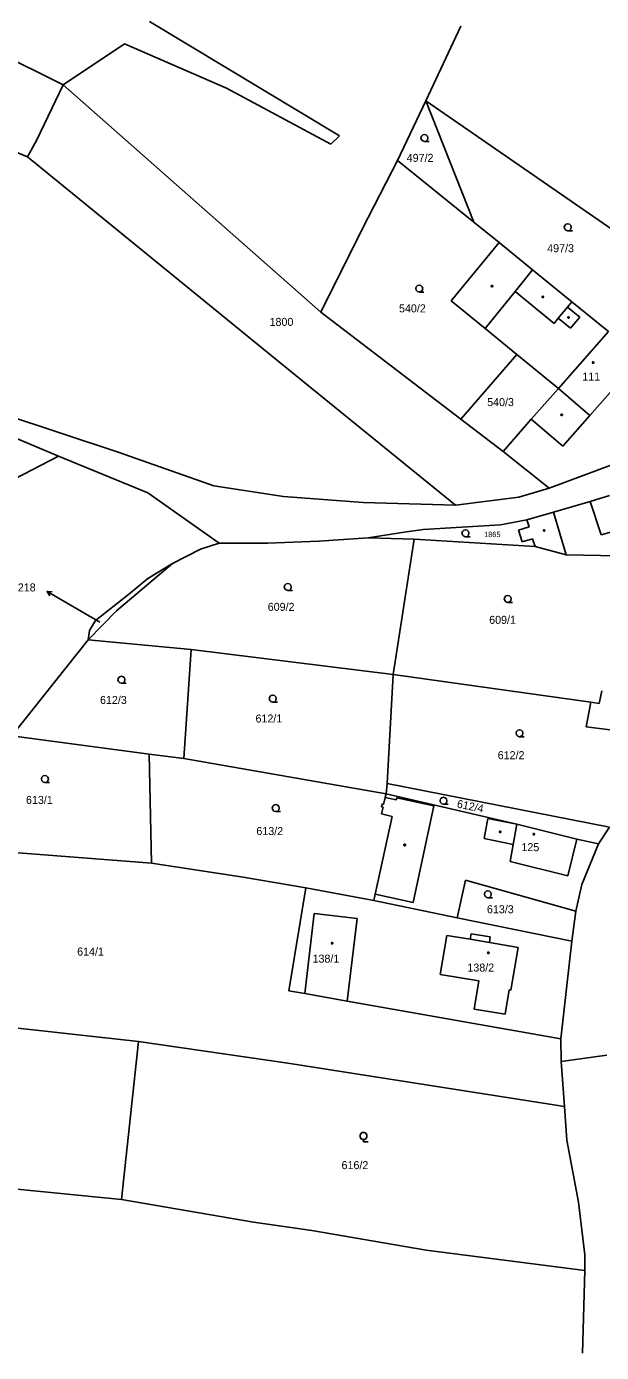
# Model space of a CAD drawing. Extents: x -802857 to -799647, y -1020285 to -1015884.
# Drawn here: x -801830.8 to -801708.7, y -1017921.9 to -1017640.2 of the extents above; entities that cross this region are included whole.
import ezdxf

# ---------------------------------------------------------------- set-up
doc = ezdxf.new("R2010")
doc.units = 0
for name, color, linetype in [('Default', 7, 'Continuous'), ('KN_HRANICE', 7, 'Continuous'), ('KN_KULTURY', 7, 'Continuous'), ('KN_PARCELY', 7, 'Continuous'), ('KN_SLUCKY', 7, 'Continuous')]:
    doc.layers.add(name, color=color, linetype=linetype)

# ---------------------------------------------------------------- blocks, each defined once
blk = doc.blocks.new('304')
at = {"layer": 'Default'}
blk.add_lwpolyline([(0, 0), (-0.38, 0.1), (-0.65, 0.37), (-0.75, 0.74), (-0.65, 1.11), (-0.38, 1.38), (-0.01, 1.48), (0.36, 1.38), (0.63, 1.11), (0.73, 0.73), (0.63, 0.35), (0.36, 0.08), (-0.02, -0.02), (0.98, -0.02)], dxfattribs=at)
blk = doc.blocks.new('305')
at = {"layer": 'Default'}
blk.add_lwpolyline([(0, 0.53), (-0.19, 0.53), (-0.53, 0.72), (-0.72, 1.06), (-0.72, 1.45), (-0.53, 1.79), (-0.19, 1.98), (0.2, 1.98), (0.54, 1.79), (0.73, 1.45), (0.73, 1.06), (0.54, 0.72), (0.2, 0.53), (0.01, 0.53), (0.01, 0), (1.01, 0)], dxfattribs=at)
blk = doc.blocks.new('10292')
at = {"layer": 'Default'}
blk.add_line((0, 3), (0, 0), dxfattribs=at)
blk.add_lwpolyline([(-0.5, 2), (0, 3), (0.5, 2)], dxfattribs=at)
blk = doc.blocks.new('402')
at = {"layer": 'Default'}
blk.add_lwpolyline([(0.09, 0.15), (0.18, 0), (0.09, -0.15), (-0.09, -0.15), (-0.18, 0), (-0.09, 0.15), (0.09, 0.15)], dxfattribs=at)

msp = doc.modelspace()

# ---------------------------------------------------------------- linework, layer by layer
at = {"layer": 'KN_HRANICE'}
for p, q in [((-801764.36, -1017663.46), (-801804.69, -1017639.18)), ((-801845.29, -1017641.57), (-801823.05, -1017652.62)), ((-801746.02, -1017656.03), (-801738.57, -1017640.16)), ((-801823.05, -1017652.62), (-801809.99, -1017643.91)), ((-801809.99, -1017643.91), (-801788.31, -1017653.32)), ((-801828.63, -1017664.31), (-801823.05, -1017652.62)), ((-801768.31, -1017700.89), (-801823.05, -1017652.62)), ((-801788.31, -1017653.32), (-801766.15, -1017665.27)), ((-801751.99, -1017668.71), (-801746.02, -1017656.03)), ((-801746.02, -1017656.03), (-801687.92, -1017696.18)), ((-801746.02, -1017656.03), (-801735.78, -1017681.78)), ((-801846.23, -1017661.47), (-801830.59, -1017667.95)), ((-801830.59, -1017667.95), (-801828.63, -1017664.31)), ((-801766.15, -1017665.27), (-801764.36, -1017663.46)), ((-801776.98, -1017711.6), (-801830.59, -1017667.95)), ((-801759.45, -1017683.12), (-801751.99, -1017668.71)), ((-801735.78, -1017681.78), (-801751.99, -1017668.71)), ((-801730.43, -1017686.1), (-801735.78, -1017681.78)), ((-801768.31, -1017700.89), (-801759.45, -1017683.12)), ((-801730.43, -1017686.1), (-801740.59, -1017698.54)), ((-801723.32, -1017691.93), (-801730.43, -1017686.1)), ((-801715, -1017698.75), (-801723.32, -1017691.93)), ((-801733.42, -1017704.41), (-801740.59, -1017698.54)), ((-801707.22, -1017705.04), (-801715, -1017698.75)), ((-801738.59, -1017723.62), (-801768.31, -1017700.89)), ((-801726.67, -1017709.93), (-801733.42, -1017704.41)), ((-801738.59, -1017723.62), (-801726.67, -1017709.93)), ((-801717.85, -1017717.14), (-801726.67, -1017709.93)), ((-801776.98, -1017711.6), (-801739.73, -1017741.89)), ((-801723.6, -1017723.68), (-801717.85, -1017717.14)), ((-801811.36, -1017730.69), (-801835.95, -1017722.51)), ((-801729.58, -1017730.5), (-801738.59, -1017723.62)), ((-801729.58, -1017730.5), (-801723.6, -1017723.68)), ((-801824.02, -1017731.49), (-801836.26, -1017726.37)), ((-801693.84, -1017728.66), (-801719.81, -1017738.32)), ((-801845.86, -1017742.83), (-801824.02, -1017731.49)), ((-801824.02, -1017731.49), (-801805.04, -1017739.33)), ((-801791.01, -1017737.84), (-801811.36, -1017730.69)), ((-801729.58, -1017730.5), (-801719.81, -1017738.32)), ((-801776.25, -1017740.1), (-801791.01, -1017737.84)), ((-801719.81, -1017738.32), (-801726.22, -1017740.21)), ((-801789.89, -1017750.03), (-801805.04, -1017739.33)), ((-801759.35, -1017741.33), (-801776.25, -1017740.1)), ((-801726.22, -1017740.21), (-801739.73, -1017741.89)), ((-801718.91, -1017743.43), (-801711.1, -1017741.13)), ((-801711.1, -1017741.13), (-801707, -1017739.9)), ((-801739.73, -1017741.89), (-801759.35, -1017741.33)), ((-801718.91, -1017743.43), (-801724.52, -1017745.04)), ((-801730.12, -1017746.12), (-801746.57, -1017747.12)), ((-801724.52, -1017745.04), (-801730.12, -1017746.12)), ((-801726.3, -1017747.2), (-801724.07, -1017746.54)), ((-801724.52, -1017745.04), (-801724.07, -1017746.54)), ((-801779.58, -1017749.96), (-801768.73, -1017749.57)), ((-801768.73, -1017749.57), (-801758.28, -1017748.85)), ((-801750.64, -1017747.69), (-801758.28, -1017748.85)), ((-801758.28, -1017748.85), (-801748.5, -1017749.12)), ((-801748.5, -1017749.12), (-801752.97, -1017777.87)), ((-801746.57, -1017747.12), (-801750.64, -1017747.69)), ((-801748.5, -1017749.12), (-801722.81, -1017750.73)), ((-801725.56, -1017749.71), (-801726.3, -1017747.2)), ((-801723.32, -1017749.05), (-801725.56, -1017749.71)), ((-801722.81, -1017750.73), (-801723.32, -1017749.05)), ((-801799.8, -1017754.28), (-801793.9, -1017751.26)), ((-801793.9, -1017751.26), (-801789.89, -1017750.03)), ((-801789.89, -1017750.03), (-801779.58, -1017749.96)), ((-801716.23, -1017752.46), (-801722.81, -1017750.73)), ((-801705.26, -1017752.69), (-801716.23, -1017752.46)), ((-801811.69, -1017764.37), (-801799.8, -1017754.28)), ((-801805.07, -1017757.47), (-801799.8, -1017754.28)), ((-801809.16, -1017760.87), (-801805.07, -1017757.47)), ((-801816.17, -1017766.42), (-801809.16, -1017760.87)), ((-801817.75, -1017770.54), (-801811.69, -1017764.37)), ((-801817.42, -1017768.52), (-801816.17, -1017766.42)), ((-801817.75, -1017770.54), (-801817.42, -1017768.52)), ((-801833.92, -1017790.89), (-801817.75, -1017770.54)), ((-801817.75, -1017770.54), (-801795.87, -1017772.61)), ((-801797.39, -1017795.73), (-801795.87, -1017772.61)), ((-801795.87, -1017772.61), (-801752.97, -1017777.87)), ((-801754.22, -1017801.07), (-801752.97, -1017777.87)), ((-801752.97, -1017777.87), (-801710.97, -1017783.74)), ((-801708.61, -1017781.39), (-801709.16, -1017784.06)), ((-801710.97, -1017783.74), (-801711.96, -1017789.03)), ((-801709.16, -1017784.06), (-801710.97, -1017783.74)), ((-801694.1, -1017791.18), (-801711.96, -1017789.03)), ((-801804.79, -1017794.82), (-801833.92, -1017790.89)), ((-801797.39, -1017795.73), (-801804.79, -1017794.82)), ((-801804.26, -1017817.96), (-801804.79, -1017794.82)), ((-801754.42, -1017803.26), (-801797.39, -1017795.73)), ((-801754.61, -1017804.04), (-801754.42, -1017803.26)), ((-801754.42, -1017803.26), (-801754.22, -1017801.07)), ((-801726.67, -1017809.66), (-801754.42, -1017803.26)), ((-801754.22, -1017801.07), (-801707.01, -1017810.3)), ((-801755.1, -1017806.05), (-801755.43, -1017807.51)), ((-801755.26, -1017805.4), (-801755.4, -1017805.98)), ((-801755.4, -1017805.98), (-801755.1, -1017806.05)), ((-801754.97, -1017805.49), (-801755.26, -1017805.4)), ((-801754.61, -1017804.04), (-801754.97, -1017805.49)), ((-801756.78, -1017824.59), (-801753.14, -1017808.04)), ((-801755.43, -1017807.51), (-801753.14, -1017808.04)), ((-801713.9, -1017812.87), (-801726.67, -1017809.66)), ((-801709.32, -1017813.86), (-801707.01, -1017810.3)), ((-801804.26, -1017817.96), (-801865.33, -1017813.26)), ((-801713.9, -1017812.87), (-801709.32, -1017813.86)), ((-801709.32, -1017813.86), (-801712.89, -1017822.5)), ((-801784.8, -1017820.93), (-801804.26, -1017817.96)), ((-801771.5, -1017823.2), (-801784.8, -1017820.93)), ((-801737.56, -1017821.57), (-801739.36, -1017829.55)), ((-801714.14, -1017828.18), (-801737.56, -1017821.57)), ((-801712.89, -1017822.5), (-801714.14, -1017828.18)), ((-801775.1, -1017845.07), (-801771.5, -1017823.2)), ((-801771.5, -1017823.2), (-801757.07, -1017825.91)), ((-801757.07, -1017825.91), (-801756.78, -1017824.59)), ((-801739.36, -1017829.55), (-801757.07, -1017825.91)), ((-801714.14, -1017828.18), (-801715, -1017834.56)), ((-801715, -1017834.56), (-801739.36, -1017829.55)), ((-801742.93, -1017841.6), (-801741.57, -1017833.31)), ((-801741.57, -1017833.31), (-801736.6, -1017834.15)), ((-801736.6, -1017834.15), (-801736.38, -1017832.95)), ((-801736.38, -1017832.95), (-801732.31, -1017833.62)), ((-801732.31, -1017833.62), (-801732.5, -1017834.84)), ((-801732.5, -1017834.84), (-801726.39, -1017835.87)), ((-801726.39, -1017835.87), (-801727.92, -1017844.94)), ((-801715, -1017834.56), (-801717.31, -1017855.3)), ((-801807.02, -1017855.84), (-801925.58, -1017842.7)), ((-801734.76, -1017842.95), (-801742.93, -1017841.6)), ((-801771.67, -1017845.68), (-801775.1, -1017845.07)), ((-801735.75, -1017848.99), (-801734.76, -1017842.95)), ((-801728.33, -1017844.87), (-801729.17, -1017850.07)), ((-801727.92, -1017844.94), (-801728.33, -1017844.87)), ((-801762.68, -1017847.27), (-801771.67, -1017845.68)), ((-801717.31, -1017855.3), (-801762.68, -1017847.27)), ((-801729.17, -1017850.07), (-801735.75, -1017848.99)), ((-801810.65, -1017889.4), (-801807.02, -1017855.84)), ((-801775.3, -1017860.43), (-801807.02, -1017855.84)), ((-801717.31, -1017855.3), (-801717.29, -1017860.13)), ((-801717.29, -1017860.13), (-801707.54, -1017858.79)), ((-801716.57, -1017869.69), (-801775.3, -1017860.43)), ((-801716.57, -1017869.69), (-801717.29, -1017860.13)), ((-801716.57, -1017869.69), (-801716.04, -1017876.81)), ((-801950.19, -1017875.73), (-801810.65, -1017889.4)), ((-801713.56, -1017889.96), (-801716.04, -1017876.81)), ((-801810.65, -1017889.4), (-801782.6, -1017894.22)), ((-801712.22, -1017901.18), (-801713.56, -1017889.96)), ((-801782.6, -1017894.22), (-801770.22, -1017896.03)), ((-801770.22, -1017896.03), (-801745.94, -1017900.17)), ((-801745.94, -1017900.17), (-801712.25, -1017904.5)), ((-801712.25, -1017904.5), (-801712.22, -1017901.18)), ((-801712.25, -1017904.5), (-801712.72, -1017922.03))]:
    msp.add_line(p, q, dxfattribs=at)
at = {"layer": 'KN_PARCELY'}
msp.add_line((-801815.23, -1017766.76), (-801823.86, -1017761.75), dxfattribs=at)
at = {"layer": 'KN_SLUCKY'}
for p, q in [((-801727.02, -1017696.5), (-801723.32, -1017691.93)), ((-801733.42, -1017704.41), (-801727.02, -1017696.5)), ((-801718.76, -1017703.3), (-801727.02, -1017696.5)), ((-801715, -1017698.75), (-801715.89, -1017699.83)), ((-801715.89, -1017699.83), (-801717.87, -1017702.22)), ((-801713.31, -1017701.97), (-801715.89, -1017699.83)), ((-801717.87, -1017702.22), (-801718.76, -1017703.3)), ((-801717.87, -1017702.22), (-801715.29, -1017704.35)), ((-801715.29, -1017704.35), (-801713.31, -1017701.97)), ((-801717.85, -1017717.14), (-801707.22, -1017705.04)), ((-801711.14, -1017722.87), (-801703.2, -1017713.83)), ((-801717.85, -1017717.14), (-801711.14, -1017722.87)), ((-801723.6, -1017723.68), (-801716.89, -1017729.41)), ((-801716.89, -1017729.41), (-801711.14, -1017722.87)), ((-801711.1, -1017741.13), (-801708.79, -1017748.25)), ((-801716.23, -1017752.46), (-801718.91, -1017743.43)), ((-801708.79, -1017748.25), (-801704.74, -1017747.09)), ((-801752.31, -1017804.55), (-801754.61, -1017804.04)), ((-801752.31, -1017804.55), (-801752.2, -1017804.06)), ((-801744.33, -1017805.8), (-801752.2, -1017804.06)), ((-801744.33, -1017805.8), (-801748.73, -1017826.31)), ((-801733.63, -1017812.75), (-801732.82, -1017808.47)), ((-801726.67, -1017809.66), (-801732.82, -1017808.47)), ((-801727.45, -1017814.01), (-801726.67, -1017809.66)), ((-801727.45, -1017814.01), (-801733.63, -1017812.75)), ((-801728.11, -1017817.63), (-801727.45, -1017814.01)), ((-801713.9, -1017812.87), (-801715.87, -1017820.65)), ((-801715.87, -1017820.65), (-801728.11, -1017817.63)), ((-801748.73, -1017826.31), (-801756.78, -1017824.59)), ((-801769.75, -1017828.65), (-801771.67, -1017845.68)), ((-801760.6, -1017829.73), (-801769.75, -1017828.65)), ((-801760.6, -1017829.73), (-801762.68, -1017847.27)), ((-801736.6, -1017834.15), (-801732.5, -1017834.84))]:
    msp.add_line(p, q, dxfattribs=at)

# ---------------------------------------------------------------- block references
at = {"layer": 'KN_KULTURY'}
for name, p in [('304', (-801746.29, -1017664.66)), ('304', (-801715.86, -1017683.63)), ('304', (-801747.4, -1017696.64)), ('402', (-801731.96, -1017695.4)), ('402', (-801721.17, -1017697.68)), ('402', (-801715.72, -1017702.04)), ('402', (-801710.48, -1017711.62)), ('402', (-801717.14, -1017722.76)), ('304', (-801737.58, -1017748.63)), ('402', (-801720.87, -1017747.28)), ('304', (-801775.32, -1017760.04)), ('304', (-801728.6, -1017762.57)), ('304', (-801810.65, -1017779.74)), ('304', (-801778.52, -1017783.76)), ('304', (-801726.1, -1017791.1)), ('304', (-801826.9, -1017800.83)), ('304', (-801777.88, -1017807)), ('304', (-801742.24, -1017805.45)), ('402', (-801730.23, -1017811.31)), ('402', (-801723.06, -1017811.81)), ('402', (-801750.49, -1017814.12)), ('304', (-801732.83, -1017825.31)), ('402', (-801765.9, -1017834.96)), ('402', (-801732.72, -1017837.01)), ('305', (-801759.25, -1017877.19))]:
    msp.add_blockref(name, p, dxfattribs=at)
at = {"layer": 'KN_PARCELY', "rotation": 59.87409}
msp.add_blockref('10292', (-801823.86, -1017761.75), dxfattribs=at)

# ---------------------------------------------------------------- texts
at = {"layer": 'KN_PARCELY'}
for s, height, p in [('497/2', 1.7, (-801750.07, -1017668.99)), ('497/3', 1.7, (-801720.23, -1017688.19)), ('540/2', 1.7, (-801751.7, -1017700.97)), ('1800', 1.7, (-801779.2, -1017703.84)), ('111', 1.7, (-801712.78, -1017715.47)), ('540/3', 1.7, (-801732.98, -1017720.88)), ('1865', 1.14, (-801733.64, -1017748.71)), ('2218', 1.7, (-801833.93, -1017760.25)), ('609/2', 1.7, (-801779.59, -1017764.37)), ('2218', 0.1, (-801815.22, -1017766.76)), ('609/1', 1.7, (-801732.55, -1017767.13)), ('612/3', 1.7, (-801815.21, -1017784.15)), ('612/1', 1.7, (-801782.18, -1017788.09)), ('612/2', 1.7, (-801730.74, -1017795.88)), ('613/1', 1.7, (-801830.93, -1017805.39)), ('613/2', 1.7, (-801782, -1017812)), ('125', 1.7, (-801725.7, -1017815.42)), ('613/3', 1.7, (-801733.03, -1017828.61)), ('614/1', 1.7, (-801820.06, -1017837.6)), ('138/1', 1.7, (-801770.07, -1017839.1)), ('138/2', 1.7, (-801737.18, -1017841)), ('616/2', 1.7, (-801763.91, -1017882.97))]:
    msp.add_text(s, height=height, dxfattribs=at).set_placement(p)
msp.add_text('612/4', height=1.7, rotation=348.645, dxfattribs=at).set_placement((-801739.51, -1017806.14))

doc.saveas('drawing.dxf')
